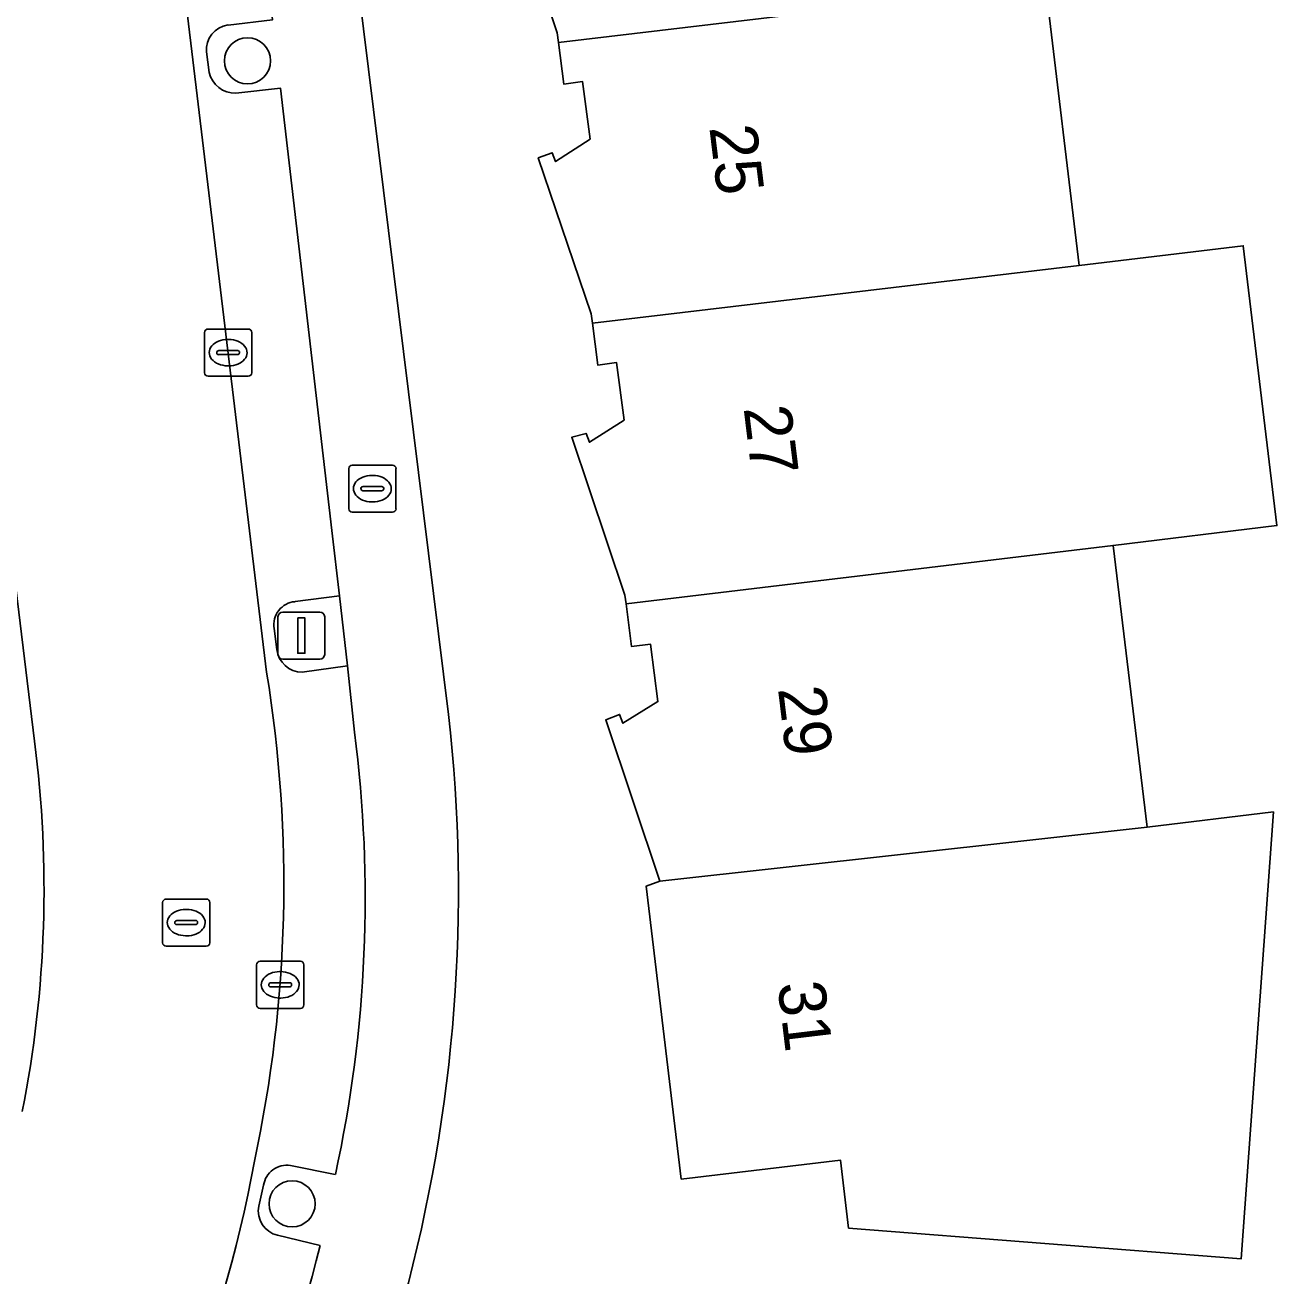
# Model space of a CAD drawing. Extents: x 162073 to 163043, y 381818 to 382561.
# Drawn here: x 162299.86 to 162326.4, y 382197.82 to 382224.36 of the extents above; entities that cross this region are included whole.
import ezdxf

# ---------------------------------------------------------------- set-up
doc = ezdxf.new("R2010")
doc.units = 0
for name, color, linetype in [('IMGEO_Boom', 7, 'Continuous'), ('IMGEO_Brandkraan', 7, 'Continuous'), ('IMGEO_Erf', 7, 'Continuous'), ('IMGEO_Kolk', 7, 'Continuous'), ('IMGEO_Lichtmast', 7, 'Continuous'), ('IMGEO_Pand', 7, 'Continuous'), ('IMGEO_Pand_nummerreeks', 7, 'Continuous'), ('IMGEO_Parkeervlak_open', 7, 'Continuous'), ('IMGEO_Rijbaan_lokaal_open', 7, 'Continuous'), ('IMGEO_Rioolput', 7, 'Continuous'), ('IMGEO_Voetpad_open', 7, 'Continuous')]:
    doc.layers.add(name, color=color, linetype=linetype)

msp = doc.modelspace()

# ---------------------------------------------------------------- linework, layer by layer
at = {"layer": 'IMGEO_Boom'}
for centre in [(162304.579, 382223.597), (162305.524, 382199.354)]:
    msp.add_circle(centre, 0.489, dxfattribs=at)
at = {"layer": 'IMGEO_Brandkraan'}
for p, q in [((162306.801, 382215.023), (162307.653, 382215.023)), ((162306.726, 382214.097), (162306.726, 382214.949)), ((162307.214, 382214.803), (162307.239, 382214.803)), ((162307.727, 382214.949), (162307.727, 382214.097)), ((162306.985, 382214.517), (162306.985, 382214.529)), ((162307.423, 382214.48), (162307.025, 382214.48)), ((162307.028, 382214.566), (162307.426, 382214.566)), ((162307.469, 382214.529), (162307.469, 382214.517)), ((162307.237, 382214.243), (162307.212, 382214.243)), ((162307.653, 382214.023), (162306.801, 382214.023))]:
    msp.add_line(p, q, dxfattribs=at)
for points in [[(162306.801, 382215.023), (162307.653, 382215.023)], [(162306.726, 382214.097), (162306.726, 382214.949)], [(162307.727, 382214.949), (162307.727, 382214.097)], [(162307.653, 382214.023), (162306.801, 382214.023)]]:
    msp.add_lwpolyline(points, dxfattribs=at)
for centre, radius, start, end in [((162306.803, 382214.947), 0.0765, 91.552, 178.448), ((162306.803, 382214.947), 0.0765, 91.552, 178.448), ((162307.651, 382214.947), 0.0765, 1.552, 88.448), ((162307.651, 382214.947), 0.0765, 1.552, 88.448), ((162307.025, 382214.526), 0.0403, 85.8775, 175.7526), ((162307.022, 382214.516), 0.0366, 178.938, 274.7102), ((162307.426, 382214.523), 0.043, 264.8664, 352.4533), ((162307.43, 382214.528), 0.0386, 1.7309, 96.639), ((162306.803, 382214.099), 0.0765, 181.552, 268.448), ((162306.803, 382214.099), 0.0765, 181.552, 268.448), ((162307.651, 382214.099), 0.0765, 271.552, 358.448), ((162307.651, 382214.099), 0.0765, 271.552, 358.448)]:
    msp.add_arc(centre, radius, start, end, dxfattribs=at)
for centre, major_axis, ratio, start_param, end_param in [((162307.213, 382214.523), (-0.387, 0.002), 0.722429, 4.712389, 7.853982), ((162307.238, 382214.523), (-0.39, 0.002), 0.717154, 1.570796, 4.712389)]:
    msp.add_ellipse(centre, major_axis=major_axis, ratio=ratio, start_param=start_param, end_param=end_param, dxfattribs=at)
at = {"layer": 'IMGEO_Erf'}
for points in [[(162303.435, 382253.355), (162303.851, 382250), (162308.838, 382209.736)], [(162321.497, 382225.213), (162322.214, 382219.257), (162325.689, 382219.676), (162326.405, 382213.738), (162322.93, 382213.319), (162323.65, 382207.343), (162326.331, 382207.666), (162325.648, 382198.19), (162317.323, 382198.841), (162317.151, 382200.281), (162313.775, 382199.878), (162313.028, 382206.091), (162313.319, 382206.201), (162312.174, 382209.622), (162312.466, 382209.733), (162312.538, 382209.547), (162313.281, 382210.006), (162313.12, 382211.225), (162312.723, 382211.172), (162312.604, 382212.078), (162312.579, 382212.265), (162311.452, 382215.612), (162311.757, 382215.694), (162311.829, 382215.508), (162312.564, 382215.976), (162312.403, 382217.195), (162312.006, 382217.142), (162311.89, 382218.035), (162311.864, 382218.234), (162310.742, 382221.539), (162311.04, 382221.646), (162311.112, 382221.46), (162311.843, 382221.937), (162311.682, 382223.156), (162311.285, 382223.103), (162311.172, 382223.982), (162311.145, 382224.191), (162310.043, 382227.504)]]:
    msp.add_lwpolyline(points, dxfattribs=at)
msp.add_arc((162276.014, 382205.991), 33.037, 344.7523, 6.5095, dxfattribs=at)
at = {"layer": 'IMGEO_Kolk'}
for p, q in [((162303.743, 382217.908), (162304.595, 382217.908)), ((162303.668, 382216.982), (162303.668, 382217.834)), ((162304.156, 382217.688), (162304.181, 382217.688)), ((162304.669, 382217.834), (162304.669, 382216.982)), ((162303.927, 382217.402), (162303.927, 382217.414)), ((162304.365, 382217.365), (162303.967, 382217.365)), ((162303.97, 382217.451), (162304.368, 382217.451)), ((162304.411, 382217.414), (162304.411, 382217.402)), ((162304.179, 382217.128), (162304.154, 382217.128)), ((162304.595, 382216.908), (162303.743, 382216.908)), ((162304.772, 382203.573), (162304.772, 382204.425)), ((162304.847, 382204.499), (162305.699, 382204.499)), ((162305.773, 382204.425), (162305.773, 382203.573)), ((162305.26, 382204.279), (162305.285, 382204.279)), ((162305.031, 382203.993), (162305.031, 382204.005)), ((162305.469, 382203.956), (162305.071, 382203.956)), ((162305.074, 382204.042), (162305.472, 382204.042)), ((162305.515, 382204.005), (162305.515, 382203.993)), ((162305.283, 382203.719), (162305.258, 382203.719)), ((162305.699, 382203.499), (162304.847, 382203.499))]:
    msp.add_line(p, q, dxfattribs=at)
for points in [[(162303.743, 382217.908), (162304.595, 382217.908)], [(162303.668, 382216.982), (162303.668, 382217.834)], [(162304.669, 382217.834), (162304.669, 382216.982)], [(162304.595, 382216.908), (162303.743, 382216.908)], [(162304.772, 382203.573), (162304.772, 382204.425)], [(162304.847, 382204.499), (162305.699, 382204.499)], [(162305.773, 382204.425), (162305.773, 382203.573)], [(162305.699, 382203.499), (162304.847, 382203.499)]]:
    msp.add_lwpolyline(points, dxfattribs=at)
for centre, radius, start, end in [((162303.745, 382217.832), 0.0765, 91.552, 178.448), ((162303.745, 382217.832), 0.0765, 91.552, 178.448), ((162304.593, 382217.832), 0.0765, 1.552, 88.448), ((162304.593, 382217.832), 0.0765, 1.552, 88.448), ((162303.967, 382217.411), 0.0403, 85.8775, 175.7526), ((162303.964, 382217.401), 0.0366, 178.938, 274.7102), ((162304.368, 382217.408), 0.043, 264.8664, 352.4533), ((162304.372, 382217.413), 0.0386, 1.7309, 96.639), ((162303.745, 382216.984), 0.0765, 181.552, 268.448), ((162303.745, 382216.984), 0.0765, 181.552, 268.448), ((162304.593, 382216.984), 0.0765, 271.552, 358.448), ((162304.593, 382216.984), 0.0765, 271.552, 358.448), ((162304.849, 382204.423), 0.0765, 91.552, 178.448), ((162304.849, 382204.423), 0.0765, 91.552, 178.448), ((162305.697, 382204.423), 0.0765, 1.552, 88.448), ((162305.697, 382204.423), 0.0765, 1.552, 88.448), ((162305.071, 382204.002), 0.0403, 85.8775, 175.7526), ((162305.068, 382203.992), 0.0366, 178.938, 274.7102), ((162305.472, 382203.999), 0.043, 264.8664, 352.4533), ((162305.476, 382204.004), 0.0386, 1.7309, 96.639), ((162304.849, 382203.575), 0.0765, 181.552, 268.448), ((162304.849, 382203.575), 0.0765, 181.552, 268.448), ((162305.697, 382203.575), 0.0765, 271.552, 358.448), ((162305.697, 382203.575), 0.0765, 271.552, 358.448)]:
    msp.add_arc(centre, radius, start, end, dxfattribs=at)
for centre, major_axis, ratio, start_param, end_param in [((162304.155, 382217.408), (-0.387, 0.002), 0.722429, 4.712389, 7.853982), ((162304.18, 382217.408), (-0.39, 0.002), 0.717154, 1.570796, 4.712389), ((162305.259, 382203.999), (-0.387, 0.002), 0.722429, 4.712389, 7.853982), ((162305.284, 382203.999), (-0.39, 0.002), 0.717154, 1.570796, 4.712389)]:
    msp.add_ellipse(centre, major_axis=major_axis, ratio=ratio, start_param=start_param, end_param=end_param, dxfattribs=at)
at = {"layer": 'IMGEO_Lichtmast'}
for p, q in [((162305.225, 382211.006), (162305.225, 382211.806)), ((162305.225, 382211.806), (162305.225, 382211.006)), ((162305.325, 382211.906), (162306.115, 382211.906)), ((162306.115, 382211.906), (162305.325, 382211.906)), ((162306.215, 382211.806), (162306.215, 382211.006)), ((162306.215, 382211.006), (162306.215, 382211.806)), ((162306.115, 382210.906), (162305.325, 382210.906)), ((162305.325, 382210.906), (162306.115, 382210.906))]:
    msp.add_line(p, q, dxfattribs=at)
msp.add_lwpolyline([(162305.645, 382211.781), (162305.795, 382211.781), (162305.795, 382211.031), (162305.645, 382211.031), (162305.645, 382211.781)], dxfattribs=at)
for centre, start, end in [((162305.325, 382211.806), 90, 180), ((162305.325, 382211.806), 90, 180), ((162306.115, 382211.806), 0, 90), ((162306.115, 382211.806), 360, 90), ((162305.325, 382211.006), 180, 270), ((162305.325, 382211.006), 180, 270), ((162306.115, 382211.006), 270, 0), ((162306.115, 382211.006), 270, 0)]:
    msp.add_arc(centre, 0.1, start, end, dxfattribs=at)
at = {"layer": 'IMGEO_Pand'}
for points in [[(162311.172, 382223.982), (162321.497, 382225.213), (162320.778, 382231.184), (162310.454, 382229.94), (162310.558, 382229.07), (162310.955, 382229.123), (162311.116, 382227.904), (162310.385, 382227.426), (162310.313, 382227.612), (162310.043, 382227.504), (162311.145, 382224.191)], [(162311.172, 382223.982), (162311.285, 382223.103), (162311.682, 382223.156), (162311.843, 382221.937), (162311.112, 382221.46), (162311.04, 382221.646), (162310.742, 382221.539), (162311.864, 382218.234), (162311.89, 382218.035), (162322.214, 382219.257), (162321.497, 382225.213)], [(162311.89, 382218.035), (162312.006, 382217.142), (162312.403, 382217.195), (162312.564, 382215.976), (162311.829, 382215.508), (162311.757, 382215.694), (162311.452, 382215.612), (162312.579, 382212.265), (162312.604, 382212.078), (162322.93, 382213.319), (162326.405, 382213.738), (162325.689, 382219.676), (162322.214, 382219.257)], [(162322.93, 382213.319), (162312.604, 382212.078), (162312.723, 382211.172), (162313.12, 382211.225), (162313.281, 382210.006), (162312.538, 382209.547), (162312.466, 382209.733), (162312.174, 382209.622), (162313.319, 382206.201), (162323.65, 382207.343)], [(162326.331, 382207.666), (162323.65, 382207.343), (162313.319, 382206.201), (162313.028, 382206.091), (162313.775, 382199.878), (162317.151, 382200.281), (162317.323, 382198.841), (162325.648, 382198.19)]]:
    msp.add_lwpolyline(points, close=True, dxfattribs=at)
at = {"layer": 'IMGEO_Parkeervlak_open'}
for points in [[(162300.293, 382249.601), (162304.984, 382210.629)], [(162300.062, 382209.169), (162295.224, 382248.984)], [(162304.167, 382224.356), (162305.109, 382224.467), (162303.824, 382235.27), (162302.847, 382235.152)], [(162303.767, 382223.349), (162303.708, 382223.784)], [(162305.587, 382212.126), (162306.529, 382212.251), (162306.369, 382213.637), (162305.282, 382223.016), (162304.332, 382222.91)], [(162305.201, 382211.112), (162305.144, 382211.558)], [(162306.846, 382209.357), (162306.701, 382210.763), (162305.737, 382210.63)], [(162305.489, 382200.166), (162306.441, 382199.976)], [(162304.817, 382199.308), (162304.921, 382199.749)], [(162306.119, 382198.472), (162305.218, 382198.687)]]:
    msp.add_lwpolyline(points, dxfattribs=at)
for centre, radius, start, end in [((162304.233, 382223.833), 0.528, 97.2192, 185.2904), ((162304.32, 382223.478), 0.568, 193.0893, 271.2169), ((162305.624, 382211.64), 0.487, 94.3474, 189.7491), ((162305.739, 382211.172), 0.542, 186.3118, 269.761), ((162277.485, 382206.129), 27.865, 347.8347, 9.2934), ((162275.853, 382206.027), 24.412, 348.8591, 7.3949), ((162279.651, 382205.832), 27.423, 347.6701, 7.3858), ((162276.836, 382205.357), 28.351, 326.0304, 349.6366), ((162305.411, 382199.676), 0.496, 80.987, 171.5819), ((162305.338, 382199.205), 0.531, 168.7692, 256.9341), ((162273.681, 382206.507), 33.418, 327.4781, 346.0871)]:
    msp.add_arc(centre, radius, start, end, dxfattribs=at)
at = {"layer": 'IMGEO_Rijbaan_lokaal_open'}
for points in [[(162286.962, 382318.033), (162292.631, 382270.853), (162293.84, 382260.608), (162295.103, 382250), (162295.224, 382248.984), (162300.062, 382209.169)], [(162304.984, 382210.629), (162300.293, 382249.601), (162300.247, 382250), (162299.951, 382252.576)]]:
    msp.add_lwpolyline(points, dxfattribs=at)
for centre, radius, start, end in [((162277.485, 382206.129), 27.865, 347.8347, 9.2934), ((162275.853, 382206.027), 24.412, 348.8591, 7.3949), ((162276.836, 382205.357), 28.351, 326.0304, 349.6366)]:
    msp.add_arc(centre, radius, start, end, dxfattribs=at)
at = {"layer": 'IMGEO_Rioolput'}
for p, q in [((162302.779, 382204.893), (162302.779, 382205.745)), ((162302.854, 382205.819), (162303.706, 382205.819)), ((162303.78, 382205.745), (162303.78, 382204.893)), ((162303.267, 382205.599), (162303.292, 382205.599)), ((162303.038, 382205.313), (162303.038, 382205.325)), ((162303.476, 382205.276), (162303.078, 382205.276)), ((162303.081, 382205.362), (162303.479, 382205.362)), ((162303.522, 382205.325), (162303.522, 382205.313)), ((162303.29, 382205.039), (162303.265, 382205.039)), ((162303.706, 382204.819), (162302.854, 382204.819))]:
    msp.add_line(p, q, dxfattribs=at)
for points in [[(162302.779, 382204.893), (162302.779, 382205.745)], [(162302.854, 382205.819), (162303.706, 382205.819)], [(162303.78, 382205.745), (162303.78, 382204.893)], [(162303.706, 382204.819), (162302.854, 382204.819)]]:
    msp.add_lwpolyline(points, dxfattribs=at)
for centre, radius, start, end in [((162302.856, 382205.743), 0.0765, 91.552, 178.448), ((162302.856, 382205.743), 0.0765, 91.552, 178.448), ((162303.704, 382205.743), 0.0765, 1.552, 88.448), ((162303.704, 382205.743), 0.0765, 1.552, 88.448), ((162303.078, 382205.322), 0.0403, 85.8775, 175.7526), ((162303.075, 382205.312), 0.0366, 178.938, 274.7102), ((162303.479, 382205.319), 0.043, 264.8664, 352.4533), ((162303.483, 382205.324), 0.0386, 1.7309, 96.639), ((162302.856, 382204.895), 0.0765, 181.552, 268.448), ((162302.856, 382204.895), 0.0765, 181.552, 268.448), ((162303.704, 382204.895), 0.0765, 271.552, 358.448), ((162303.704, 382204.895), 0.0765, 271.552, 358.448)]:
    msp.add_arc(centre, radius, start, end, dxfattribs=at)
for centre, major_axis, ratio, start_param, end_param in [((162303.266, 382205.319), (-0.387, 0.002), 0.722429, 4.712389, 7.853982), ((162303.291, 382205.319), (-0.39, 0.002), 0.717154, 1.570796, 4.712389)]:
    msp.add_ellipse(centre, major_axis=major_axis, ratio=ratio, start_param=start_param, end_param=end_param, dxfattribs=at)
at = {"layer": 'IMGEO_Voetpad_open'}
for points in [[(162308.838, 382209.736), (162303.851, 382250), (162303.435, 382253.355)], [(162302.847, 382235.152), (162303.824, 382235.27), (162305.109, 382224.467), (162304.167, 382224.356)], [(162303.708, 382223.784), (162303.767, 382223.349)], [(162304.332, 382222.91), (162305.282, 382223.016), (162306.369, 382213.637), (162306.529, 382212.251), (162306.701, 382210.763), (162306.846, 382209.357)], [(162305.737, 382210.63), (162306.701, 382210.763), (162306.529, 382212.251), (162305.587, 382212.126)], [(162305.144, 382211.558), (162305.201, 382211.112)], [(162306.441, 382199.976), (162305.489, 382200.166)], [(162304.921, 382199.749), (162304.817, 382199.308)], [(162305.218, 382198.687), (162306.119, 382198.472)]]:
    msp.add_lwpolyline(points, dxfattribs=at)
for centre, radius, start, end in [((162304.233, 382223.833), 0.528, 97.2192, 185.2904), ((162304.32, 382223.478), 0.568, 193.0893, 271.2169), ((162305.624, 382211.64), 0.487, 94.3474, 189.7491), ((162305.739, 382211.172), 0.542, 186.3118, 269.761), ((162276.014, 382205.991), 33.037, 344.7523, 6.5095), ((162279.651, 382205.832), 27.423, 347.6701, 7.3858), ((162305.411, 382199.676), 0.496, 80.987, 171.5819), ((162305.338, 382199.205), 0.531, 168.7692, 256.9341), ((162273.681, 382206.507), 33.418, 327.4781, 346.0871)]:
    msp.add_arc(centre, radius, start, end, dxfattribs=at)

# ---------------------------------------------------------------- texts
at = {"layer": 'IMGEO_Pand_nummerreeks'}
for s, rotation, p in [('25', 276.969, (162314.369, 382222.187)), ('27', 276.969, (162315.096, 382216.235)), ('29', 276.967, (162315.824, 382210.283)), ('31', 276.8581, (162315.814, 382204.022))]:
    msp.add_text(s, height=1, rotation=rotation, dxfattribs=at).set_placement(p)

doc.saveas('drawing.dxf')
